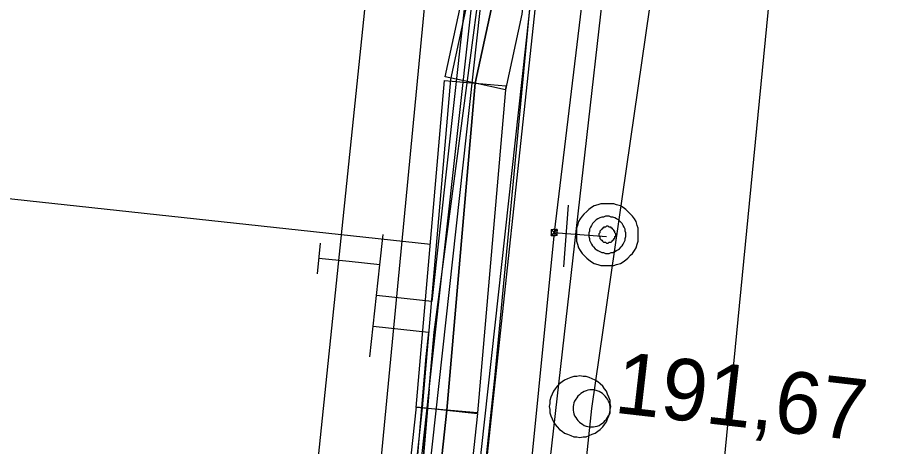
# Model space of a CAD drawing. Extents: x -746464 to -745690, y -1051581 to -1049993.
# Drawn here: x -746139.32 to -746125.2, y -1050890.53 to -1050883.56 of the extents above; entities that cross this region are included whole.
import ezdxf

# ---------------------------------------------------------------- set-up
doc = ezdxf.new("R2010")
doc.units = 0
for name, color, linetype in [('04_CETIN_neprovozovane', 7, 'Continuous'), ('04_CETIN_sdelovaci_podzem', 7, 'Continuous'), ('37_TVNET_sdelovaci_televizni kabely', 7, 'Continuous'), ('45_Eltodo_napajeci_kabel_NN', 7, 'Continuous'), ('45_Eltodo_vedeni_NN_zemni', 7, 'Continuous'), ('48_Prazs_plynarenska_STL', 7, 'Continuous'), ('51_PVaK_kanal_jednotna_overena poloha_rad', 7, 'Continuous'), ('51_PVaK_kanal_negravitacni_overena poloha', 7, 'Continuous'), ('51_PVaK_kanal_objekty', 7, 'Continuous'), ('51_PVaK_kanal_popisy', 7, 'Continuous'), ('51_PVaK_vodovod_chranicky_objekty', 7, 'Continuous'), ('51_PVaK_vodovod_NEPROVOZUJE PVK_neoverene poloha', 7, 'Continuous'), ('55_PREdi_chranicky', 7, 'Continuous'), ('55_PREdi_NN', 7, 'Continuous'), ('55_PREdi_NN_pripojovaci_misto', 7, 'Continuous'), ('55_PREdi_stavby_popisy', 7, 'Continuous'), ('55_PREdi_VN', 7, 'Continuous'), ('55_PREdi_ZRUSENE_elektro', 7, 'Continuous')]:
    doc.layers.add(name, color=color, linetype=linetype)

msp = doc.modelspace()

# ---------------------------------------------------------------- linework, layer by layer
at = {"layer": '04_CETIN_neprovozovane'}
msp.add_lwpolyline([(-746139.1, -1050955.08), (-746136.85, -1050934.54), (-746132.62, -1050899.26), (-746131.56, -1050889.42), (-746130.25, -1050875.59), (-746129.56, -1050868.17)], dxfattribs=at)
at = {"layer": '04_CETIN_sdelovaci_podzem'}
for points in [[(-746133.09, -1050894.99), (-746132.63, -1050889.6), (-746132.55, -1050888.67), (-746131.75, -1050882.66), (-746131.25, -1050877.79)], [(-746132.55, -1050888.67), (-746131.75, -1050882.66)], [(-746132.63, -1050889.6), (-746133.09, -1050894.99)]]:
    msp.add_lwpolyline(points, dxfattribs=at)
at = {"layer": '37_TVNET_sdelovaci_televizni kabely'}
for points in [[(-745984.595, -1050626.363), (-746079.15, -1050602.616), (-746117.902, -1050728.62), (-746140.499, -1050964.785), (-746150.343, -1051014.385), (-746134.374, -1051025.766), (-746053.56, -1051028.358)], [(-746146.492, -1050906.983), (-746136.117, -1050906.983), (-746133.294, -1050879.776), (-746144.341, -1050879.885)]]:
    msp.add_lwpolyline(points, dxfattribs=at)
at = {"layer": '45_Eltodo_napajeci_kabel_NN'}
msp.add_lwpolyline([(-746165.45, -1051019.12), (-746165.712, -1051018.023), (-746163.467, -1051013.836), (-746155.197, -1051018.912), (-746150.32, -1051019.043), (-746148.604, -1051010.158), (-746143.982, -1050988.385), (-746139.729, -1050968.164), (-746137.496, -1050944.441), (-746135.374, -1050923.74), (-746132.775, -1050899.638), (-746130.229, -1050876.488), (-746127.576, -1050852.278), (-746125.136, -1050831.143), (-746122.376, -1050803.534), (-746119.744, -1050781.489), (-746120.222, -1050780.456), (-746117.893, -1050761.331)], dxfattribs=at)
at = {"layer": '45_Eltodo_vedeni_NN_zemni'}
msp.add_lwpolyline([(-746133.57, -1050899.551), (-746131.024, -1050876.401)], dxfattribs=at)
at = {"layer": '48_Prazs_plynarenska_STL'}
msp.add_lwpolyline([(-746128.924, -1050901.967), (-746128.119, -1050893.674), (-746126.8, -1050880.15), (-746126.425, -1050876.727), (-746123.398, -1050849.062), (-746122.397, -1050839.917), (-746121.85, -1050834.92), (-746119.64, -1050819.16), (-746118.456, -1050807.673), (-746117.44, -1050797.41), (-746116.892, -1050792.088), (-746116.554, -1050788.806), (-746115.818, -1050781.644), (-746115.679, -1050780.281), (-746115.164, -1050775.276), (-746114.581, -1050769.606)], dxfattribs=at)
at = {"layer": '51_PVaK_kanal_jednotna_overena poloha_rad'}
msp.add_lwpolyline([(-746132.48, -1050906.76), (-746131.225, -1050895.713), (-746128.653, -1050873.059), (-746127.4, -1050862.03)], dxfattribs=at)
at = {"layer": '51_PVaK_kanal_negravitacni_overena poloha'}
for points in [[(-746122.42, -1050820.88), (-746122.58, -1050824.12), (-746123.99, -1050836.59), (-746126.03, -1050856.03), (-746128.8, -1050881.67), (-746129.99, -1050889.91)], [(-746129.99, -1050889.91), (-746131.16, -1050900.96), (-746132.82, -1050919.05), (-746135.39, -1050940.9), (-746136.9, -1050954.59)]]:
    msp.add_lwpolyline(points, dxfattribs=at)
at = {"layer": '51_PVaK_kanal_objekty'}
for points in [[(-746129.68, -1050889.88), (-746129.69, -1050889.83), (-746129.69, -1050889.78), (-746129.71, -1050889.73), (-746129.73, -1050889.68), (-746129.75, -1050889.63), (-746129.78, -1050889.59), (-746129.81, -1050889.55), (-746129.85, -1050889.51), (-746129.89, -1050889.48), (-746129.93, -1050889.45), (-746129.98, -1050889.43), (-746130.03, -1050889.41), (-746130.08, -1050889.39), (-746130.13, -1050889.39), (-746130.18, -1050889.38), (-746130.23, -1050889.39), (-746130.28, -1050889.39), (-746130.33, -1050889.41), (-746130.38, -1050889.43), (-746130.43, -1050889.45), (-746130.47, -1050889.48), (-746130.51, -1050889.51), (-746130.55, -1050889.55), (-746130.58, -1050889.59), (-746130.61, -1050889.63), (-746130.63, -1050889.68), (-746130.65, -1050889.73), (-746130.67, -1050889.78), (-746130.67, -1050889.83), (-746130.68, -1050889.88), (-746130.67, -1050889.93), (-746130.67, -1050889.98), (-746130.65, -1050890.03), (-746130.63, -1050890.08), (-746130.61, -1050890.13), (-746130.58, -1050890.17), (-746130.55, -1050890.21), (-746130.51, -1050890.25), (-746130.47, -1050890.28), (-746130.43, -1050890.31), (-746130.38, -1050890.33), (-746130.33, -1050890.35), (-746130.28, -1050890.37), (-746130.23, -1050890.37), (-746130.18, -1050890.38), (-746130.13, -1050890.37), (-746130.08, -1050890.37), (-746130.03, -1050890.35), (-746129.98, -1050890.33), (-746129.93, -1050890.31), (-746129.89, -1050890.28), (-746129.85, -1050890.25), (-746129.81, -1050890.21), (-746129.78, -1050890.17), (-746129.75, -1050890.13), (-746129.73, -1050890.08), (-746129.71, -1050890.03), (-746129.69, -1050889.98), (-746129.69, -1050889.93), (-746129.68, -1050889.88)], [(-746129.69, -1050889.91), (-746129.69, -1050889.88), (-746129.696, -1050889.85), (-746129.702, -1050889.82), (-746129.714, -1050889.79), (-746129.732, -1050889.76), (-746129.75, -1050889.736), (-746129.768, -1050889.712), (-746129.792, -1050889.688), (-746129.816, -1050889.67), (-746129.84, -1050889.652), (-746129.87, -1050889.634), (-746129.9, -1050889.622), (-746129.93, -1050889.616), (-746129.96, -1050889.61), (-746129.99, -1050889.61), (-746130.02, -1050889.61), (-746130.05, -1050889.616), (-746130.08, -1050889.622), (-746130.11, -1050889.634), (-746130.14, -1050889.652), (-746130.164, -1050889.67), (-746130.188, -1050889.688), (-746130.212, -1050889.712), (-746130.23, -1050889.736), (-746130.248, -1050889.76), (-746130.266, -1050889.79), (-746130.278, -1050889.82), (-746130.284, -1050889.85), (-746130.29, -1050889.88), (-746130.29, -1050889.91), (-746130.29, -1050889.94), (-746130.284, -1050889.97), (-746130.278, -1050890), (-746130.266, -1050890.03), (-746130.248, -1050890.06), (-746130.23, -1050890.084), (-746130.212, -1050890.108), (-746130.188, -1050890.132), (-746130.164, -1050890.15), (-746130.14, -1050890.168), (-746130.11, -1050890.186), (-746130.08, -1050890.198), (-746130.05, -1050890.204), (-746130.02, -1050890.21), (-746129.99, -1050890.21), (-746129.96, -1050890.21), (-746129.93, -1050890.204), (-746129.9, -1050890.198), (-746129.87, -1050890.186), (-746129.84, -1050890.168), (-746129.816, -1050890.15), (-746129.792, -1050890.132), (-746129.768, -1050890.108), (-746129.75, -1050890.084), (-746129.732, -1050890.06), (-746129.714, -1050890.03), (-746129.702, -1050890), (-746129.696, -1050889.97), (-746129.69, -1050889.94), (-746129.69, -1050889.91)]]:
    msp.add_lwpolyline(points, dxfattribs=at)
at = {"layer": '51_PVaK_vodovod_chranicky_objekty'}
for p, q in [((-746130.44, -1050887.61), (-746130.365, -1050886.61)), ((-746130.648, -1050887.104), (-746130.548, -1050887.004)), ((-746130.648, -1050887.004), (-746130.548, -1050887.104)), ((-746130.648, -1050887.004), (-746130.648, -1050887.024)), ((-746130.648, -1050887.004), (-746130.628, -1050887.004)), ((-746130.548, -1050887.004), (-746130.568, -1050887.004)), ((-746130.548, -1050887.004), (-746130.548, -1050887.024)), ((-746130.648, -1050887.104), (-746130.648, -1050887.084)), ((-746130.648, -1050887.104), (-746130.628, -1050887.104)), ((-746130.548, -1050887.104), (-746130.568, -1050887.104)), ((-746130.548, -1050887.104), (-746130.548, -1050887.084))]:
    msp.add_line(p, q, dxfattribs=at)
for points in [[(-746129.235, -1050887.089), (-746129.235, -1050887.044), (-746129.235, -1050886.983), (-746129.25, -1050886.938), (-746129.265, -1050886.877), (-746129.296, -1050886.832), (-746129.326, -1050886.786), (-746129.356, -1050886.756), (-746129.402, -1050886.711), (-746129.432, -1050886.68), (-746129.478, -1050886.65), (-746129.523, -1050886.62), (-746129.584, -1050886.605), (-746129.629, -1050886.589), (-746129.69, -1050886.589), (-746129.735, -1050886.589), (-746129.796, -1050886.589), (-746129.841, -1050886.589), (-746129.887, -1050886.605), (-746129.947, -1050886.62), (-746129.993, -1050886.65), (-746130.038, -1050886.68), (-746130.068, -1050886.711), (-746130.114, -1050886.756), (-746130.144, -1050886.786), (-746130.175, -1050886.832), (-746130.205, -1050886.877), (-746130.22, -1050886.938), (-746130.235, -1050886.983), (-746130.235, -1050887.044), (-746130.235, -1050887.089), (-746130.235, -1050887.15), (-746130.235, -1050887.195), (-746130.22, -1050887.241), (-746130.205, -1050887.302), (-746130.175, -1050887.347), (-746130.144, -1050887.392), (-746130.114, -1050887.423), (-746130.068, -1050887.468), (-746130.038, -1050887.498), (-746129.993, -1050887.529), (-746129.947, -1050887.559), (-746129.887, -1050887.574), (-746129.841, -1050887.589), (-746129.796, -1050887.589), (-746129.735, -1050887.589), (-746129.69, -1050887.589), (-746129.629, -1050887.589), (-746129.584, -1050887.574), (-746129.523, -1050887.559), (-746129.478, -1050887.529), (-746129.432, -1050887.498), (-746129.402, -1050887.468), (-746129.356, -1050887.423), (-746129.326, -1050887.392), (-746129.296, -1050887.347), (-746129.265, -1050887.302), (-746129.25, -1050887.241), (-746129.235, -1050887.195), (-746129.235, -1050887.15), (-746129.235, -1050887.089)], [(-746129.432, -1050887.089), (-746129.432, -1050887.059), (-746129.447, -1050887.029), (-746129.447, -1050886.998), (-746129.462, -1050886.968), (-746129.478, -1050886.938), (-746129.493, -1050886.908), (-746129.508, -1050886.892), (-746129.538, -1050886.862), (-746129.553, -1050886.847), (-746129.584, -1050886.832), (-746129.614, -1050886.817), (-746129.644, -1050886.802), (-746129.675, -1050886.802), (-746129.705, -1050886.786), (-746129.735, -1050886.786), (-746129.765, -1050886.786), (-746129.796, -1050886.802), (-746129.826, -1050886.802), (-746129.856, -1050886.817), (-746129.887, -1050886.832), (-746129.917, -1050886.847), (-746129.932, -1050886.862), (-746129.962, -1050886.892), (-746129.978, -1050886.908), (-746129.993, -1050886.938), (-746130.008, -1050886.968), (-746130.023, -1050886.998), (-746130.023, -1050887.029), (-746130.038, -1050887.059), (-746130.038, -1050887.089), (-746130.038, -1050887.12), (-746130.023, -1050887.15), (-746130.023, -1050887.18), (-746130.008, -1050887.211), (-746129.993, -1050887.241), (-746129.978, -1050887.271), (-746129.962, -1050887.286), (-746129.932, -1050887.317), (-746129.917, -1050887.332), (-746129.887, -1050887.347), (-746129.856, -1050887.362), (-746129.826, -1050887.377), (-746129.796, -1050887.377), (-746129.765, -1050887.392), (-746129.735, -1050887.392), (-746129.705, -1050887.392), (-746129.675, -1050887.377), (-746129.644, -1050887.377), (-746129.614, -1050887.362), (-746129.584, -1050887.347), (-746129.553, -1050887.332), (-746129.538, -1050887.317), (-746129.508, -1050887.286), (-746129.493, -1050887.271), (-746129.478, -1050887.241), (-746129.462, -1050887.211), (-746129.447, -1050887.18), (-746129.447, -1050887.15), (-746129.432, -1050887.12), (-746129.432, -1050887.089)], [(-746130.548, -1050887.054), (-746130.548, -1050887.049), (-746130.549, -1050887.044), (-746130.55, -1050887.039), (-746130.552, -1050887.034), (-746130.555, -1050887.029), (-746130.558, -1050887.025), (-746130.561, -1050887.021), (-746130.565, -1050887.017), (-746130.569, -1050887.014), (-746130.573, -1050887.011), (-746130.578, -1050887.008), (-746130.583, -1050887.006), (-746130.588, -1050887.005), (-746130.593, -1050887.004), (-746130.598, -1050887.004), (-746130.603, -1050887.004), (-746130.608, -1050887.005), (-746130.613, -1050887.006), (-746130.618, -1050887.008), (-746130.623, -1050887.011), (-746130.627, -1050887.014), (-746130.631, -1050887.017), (-746130.635, -1050887.021), (-746130.638, -1050887.025), (-746130.641, -1050887.029), (-746130.644, -1050887.034), (-746130.646, -1050887.039), (-746130.647, -1050887.044), (-746130.648, -1050887.049), (-746130.648, -1050887.054), (-746130.648, -1050887.059), (-746130.647, -1050887.064), (-746130.646, -1050887.069), (-746130.644, -1050887.074), (-746130.641, -1050887.079), (-746130.638, -1050887.083), (-746130.635, -1050887.087), (-746130.631, -1050887.091), (-746130.627, -1050887.094), (-746130.623, -1050887.097), (-746130.618, -1050887.1), (-746130.613, -1050887.102), (-746130.608, -1050887.103), (-746130.603, -1050887.104), (-746130.598, -1050887.104), (-746130.593, -1050887.104), (-746130.588, -1050887.103), (-746130.583, -1050887.102), (-746130.578, -1050887.1), (-746130.573, -1050887.097), (-746130.569, -1050887.094), (-746130.565, -1050887.091), (-746130.561, -1050887.087), (-746130.558, -1050887.083), (-746130.555, -1050887.079), (-746130.552, -1050887.074), (-746130.55, -1050887.069), (-746130.549, -1050887.064), (-746130.548, -1050887.059), (-746130.548, -1050887.054)], [(-746129.599, -1050887.089), (-746129.599, -1050887.074), (-746129.614, -1050887.059), (-746129.614, -1050887.044), (-746129.614, -1050887.029), (-746129.629, -1050887.029), (-746129.629, -1050887.014), (-746129.644, -1050886.998), (-746129.659, -1050886.983), (-746129.675, -1050886.983), (-746129.675, -1050886.968), (-746129.69, -1050886.968), (-746129.705, -1050886.968), (-746129.72, -1050886.953), (-746129.735, -1050886.953), (-746129.75, -1050886.953), (-746129.765, -1050886.968), (-746129.781, -1050886.968), (-746129.796, -1050886.968), (-746129.796, -1050886.983), (-746129.811, -1050886.983), (-746129.826, -1050886.998), (-746129.841, -1050887.014), (-746129.856, -1050887.029), (-746129.856, -1050887.044), (-746129.856, -1050887.059), (-746129.872, -1050887.074), (-746129.872, -1050887.089), (-746129.872, -1050887.105), (-746129.856, -1050887.12), (-746129.856, -1050887.135), (-746129.856, -1050887.15), (-746129.841, -1050887.165), (-746129.826, -1050887.18), (-746129.811, -1050887.195), (-746129.796, -1050887.211), (-746129.781, -1050887.211), (-746129.765, -1050887.211), (-746129.75, -1050887.226), (-746129.735, -1050887.226), (-746129.72, -1050887.226), (-746129.705, -1050887.211), (-746129.69, -1050887.211), (-746129.675, -1050887.211), (-746129.659, -1050887.195), (-746129.644, -1050887.18), (-746129.629, -1050887.165), (-746129.629, -1050887.15), (-746129.614, -1050887.15), (-746129.614, -1050887.135), (-746129.614, -1050887.12), (-746129.599, -1050887.105), (-746129.599, -1050887.089)]]:
    msp.add_lwpolyline(points, dxfattribs=at)
at = {"layer": '51_PVaK_vodovod_NEPROVOZUJE PVK_neoverene poloha'}
for p, q in [((-746130.599, -1050887.055), (-746131.754, -1050898.624)), ((-746130.599, -1050887.055), (-746130.4, -1050887.07)), ((-746130.4, -1050887.07), (-746129.75, -1050887.12))]:
    msp.add_line(p, q, dxfattribs=at)
msp.add_lwpolyline([(-746119.36, -1050777.72), (-746119.951, -1050786.603), (-746121.099, -1050796.35), (-746122.392, -1050810.364), (-746123.931, -1050826.638), (-746127.054, -1050855.254), (-746129.164, -1050875.152), (-746130.599, -1050887.055)], dxfattribs=at)
at = {"layer": '55_PREdi_chranicky'}
for points in [[(-746128.9, -1050858.11), (-746128.402, -1050858.16), (-746128.973, -1050863.843), (-746129.773, -1050870.836), (-746130.553, -1050877.893), (-746131.125, -1050883.509), (-746131.391, -1050884.736), (-746131.88, -1050884.63), (-746132.369, -1050884.524), (-746132.115, -1050883.351), (-746131.547, -1050877.787), (-746130.767, -1050870.724), (-746129.967, -1050863.737), (-746129.398, -1050858.06), (-746128.9, -1050858.11)], [(-746131.88, -1050884.63), (-746131.382, -1050884.673), (-746131.842, -1050889.983), (-746132.34, -1050889.94), (-746132.838, -1050889.897), (-746132.378, -1050884.587), (-746131.88, -1050884.63)], [(-746132.34, -1050889.94), (-746131.843, -1050889.994), (-746132.473, -1050895.814), (-746132.97, -1050895.76), (-746133.467, -1050895.706), (-746132.837, -1050889.886), (-746132.34, -1050889.94)]]:
    msp.add_lwpolyline(points, close=True, dxfattribs=at)
at = {"layer": '55_PREdi_NN'}
for points in [[(-746079.707, -1050608.094), (-746081.337, -1050613.521), (-746088.598, -1050639.168), (-746100.883, -1050680.307), (-746109.804, -1050710.935), (-746113.542, -1050724.97), (-746114.797, -1050736.143), (-746116.957, -1050755.942), (-746121.273, -1050791.507), (-746121.329, -1050792.488), (-746122.44, -1050801.822), (-746124.772, -1050826.479), (-746132.514, -1050898.319), (-746135.263, -1050933.408), (-746137.115, -1050954.341), (-746141.612, -1050953.806)], [(-746136.661, -1050851.01), (-746136.586, -1050850.36), (-746128.508, -1050851.306), (-746132.585, -1050888.176), (-746133.484, -1050888.078)], [(-746128.424, -1050850.797), (-746130.254, -1050868.095), (-746132.604, -1050889.306), (-746136.454, -1050924.495), (-746139.792, -1050954.992)], [(-746133.592, -1050889.073), (-746133.538, -1050888.576), (-746133.484, -1050888.078), (-746133.43, -1050887.581), (-746133.376, -1050887.084)], [(-746133.43, -1050887.581), (-746133.927, -1050887.527)], [(-746133.538, -1050888.576), (-746132.639, -1050888.674), (-746132.683, -1050889.066), (-746134.269, -1050907.802), (-746135.709, -1050907.68)]]:
    msp.add_lwpolyline(points, dxfattribs=at)
at = {"layer": '55_PREdi_NN_pripojovaci_misto'}
for p, q in [((-746134.398, -1050887.226), (-746134.45, -1050887.723)), ((-746133.927, -1050887.527), (-746134.424, -1050887.475))]:
    msp.add_line(p, q, dxfattribs=at)
at = {"layer": '55_PREdi_stavby_popisy'}
msp.add_lwpolyline([(-746150.309, -1050885.317), (-746149.316, -1050885.436), (-746132.608, -1050887.242)], dxfattribs=at)
at = {"layer": '55_PREdi_VN'}
for points in [[(-746142.76, -1050982.05), (-746141.66, -1050970.61), (-746140.95, -1050966.94), (-746140.63, -1050965.04), (-746139.79, -1050956.27), (-746139.53, -1050954.37), (-746139.01, -1050951.72), (-746137.09, -1050934.25), (-746135.64, -1050920.87), (-746134.47, -1050909.58), (-746133.32, -1050900.25), (-746132.97, -1050895.76), (-746132.34, -1050889.94), (-746131.88, -1050884.63), (-746131.62, -1050883.43)], [(-746131.62, -1050883.43), (-746131.88, -1050884.63), (-746132.34, -1050889.94), (-746132.97, -1050895.76), (-746133.32, -1050900.25), (-746134.47, -1050909.58), (-746135.64, -1050920.87), (-746137.09, -1050934.25), (-746139.01, -1050951.72), (-746139.53, -1050954.37), (-746139.79, -1050956.27), (-746140.63, -1050965.04), (-746140.95, -1050966.94), (-746141.66, -1050970.61), (-746142.086, -1050975.043)]]:
    msp.add_lwpolyline(points, dxfattribs=at)
at = {"layer": '55_PREdi_ZRUSENE_elektro'}
msp.add_lwpolyline([(-746142.688, -1050977.425), (-746142.056, -1050970.553), (-746141.344, -1050966.869), (-746141.027, -1050964.988), (-746140.187, -1050956.224), (-746139.925, -1050954.304), (-746139.406, -1050951.66), (-746137.488, -1050934.207), (-746136.038, -1050920.828), (-746134.867, -1050909.535), (-746133.718, -1050900.21), (-746133.368, -1050895.723), (-746132.738, -1050889.901), (-746132.276, -1050884.57), (-746132.016, -1050883.367)], dxfattribs=at)

# ---------------------------------------------------------------- texts
at = {"layer": '51_PVaK_kanal_popisy'}
msp.add_text('191,67', height=1, rotation=353.4537, dxfattribs=at).set_placement((-746129.641, -1050889.977))

doc.saveas('drawing.dxf')
